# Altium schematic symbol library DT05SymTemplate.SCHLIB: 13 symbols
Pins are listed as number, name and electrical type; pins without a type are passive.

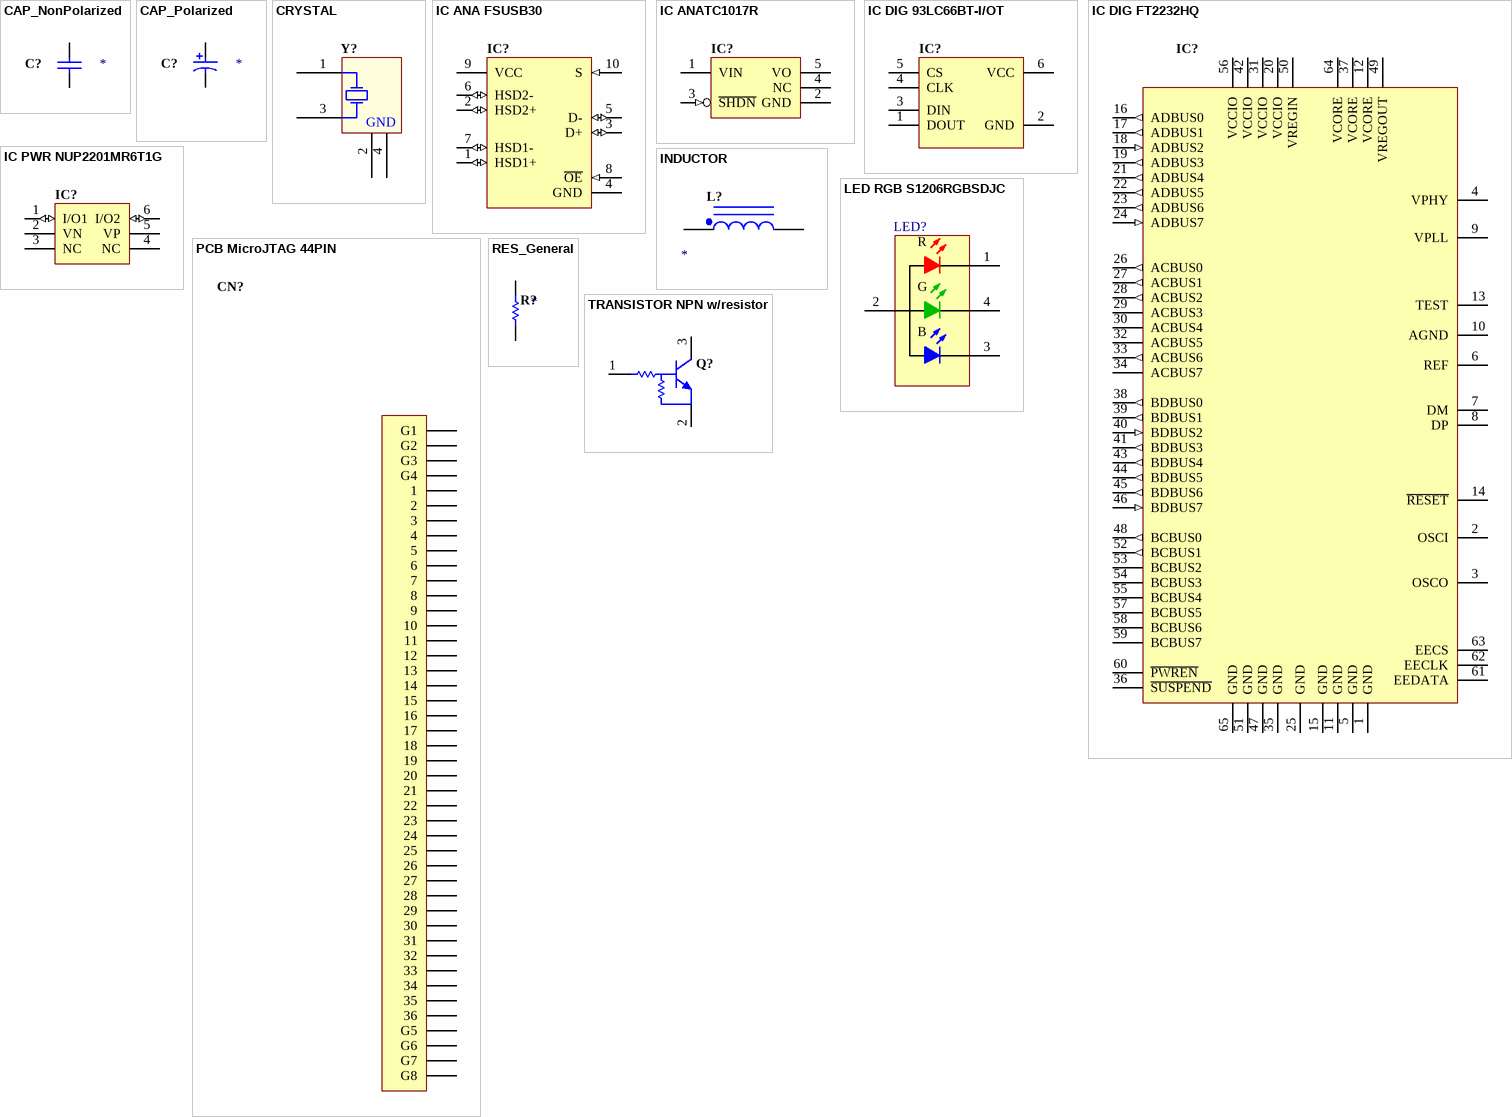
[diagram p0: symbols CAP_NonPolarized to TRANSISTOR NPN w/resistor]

## CAP_NonPolarized
designator C?  (value not drawn)
pins: 1, 2

## CAP_Polarized
designator C?  (value not drawn)
pins: 1, 2

## CRYSTAL
designator Y?  (value not drawn)
pins: 1 X1, 2 GND, 3 X2, 4 GND

## IC ANA FSUSB30
designator IC?  (value not drawn)
IC,Analog,FSUB30,Low-Power, Two-Port, High-Speed USB2.0 Switch
pins: 1 HSD1+ (io) "Data Inport", 2 HSD2+ (io) "Data Inport", 3 D+ (io) "Data Inport", 4 GND (power) "Ground", 5 D- (io) "Data Inport", 6 HSD2- (io) "Data Inport", 7 HSD1- (io) "Data Inport", 8 ~{OE} (in) "Bus Switch Enable", 9 VCC (power) "Supply", 10 S (in) "Select Input"

## IC ANATC1017R
designator IC?, comment IC ANA TC1017R  (value not drawn)
IC,Analog,XC6220B331MR-G,High Current High Speed LDO Regulator
pins: 1 VIN (power), 2 GND (power), 3 ~{SHDN} (in), 4 NC, 5 VO (power)

## IC DIG 93LC66BT-I/OT
designator IC?  (value not drawn)
IC,Digital,93LC66BT-I/OT,4K Microwire Compatible Serial EEPROM
pins: 1 DOUT, 2 GND (power), 3 DIN, 4 CLK, 5 CS (power), 6 VCC

## IC DIG FT2232HQ
designator IC?  (value not drawn)
IC,Digital,FT2232H,DUAL HIGH SPEED USB TO MULTIPURPOSE UART/FIFO IC
pins: 1 GND, 2 OSCI, 3 OSCO, 4 VPHY, 5 GND, 6 REF, 7 DM, 8 DP, 9 VPLL, 10 AGND, 11 GND, 12 VCORE, 13 TEST, 14 ~{RESET}, 15 GND, 16 ADBUS0 (out), 17 ADBUS1 (out), 18 ADBUS2 (in), 19 ADBUS3 (out), 20 VCCIO, 21 ADBUS4 (out), 22 ADBUS5 (out), 23 ADBUS6 (out), 24 ADBUS7 (in), 25 GND, 26 ACBUS0 (out), 27 ACBUS1 (out), 28 ACBUS2 (out), 29 ACBUS3, 30 ACBUS4, 31 VCCIO, 32 ACBUS5, 33 ACBUS6 (out), 34 ACBUS7, 35 GND, 36 ~{SUSPEND}, 37 VCORE, 38 BDBUS0 (out), 39 BDBUS1 (out), 40 BDBUS2 (in), 41 BDBUS3 (out), 42 VCCIO, 43 BDBUS4 (out), 44 BDBUS5 (out), 45 BDBUS6 (out), 46 BDBUS7 (in), 47 GND, 48 BCBUS0 (out), 49 VREGOUT, 50 VREGIN, 51 GND, 52 BCBUS1 (out), 53 BCBUS2, 54 BCBUS3, 55 BCBUS4, 56 VCCIO, 57 BCBUS5, 58 BCBUS6, 59 BCBUS7, 60 ~{PWREN}, 61 EEDATA, 62 EECLK, 63 EECS, 64 VCORE, 65 GND
2 alternate drawings of the same symbol

## IC PWR NUP2201MR6T1G
designator IC?  (value not drawn)
IC,Power,NUP2201MR6T1G,ESD Protection Diodes with Low Clamping Voltage,TSOP-6
pins: 1 I/O1 (io) "Input/Output 1", 2 VN (power), 3 NC, 4 NC, 5 VP (power), 6 I/O2 (io)

## INDUCTOR
designator L?  (value not drawn)
pins: 1, 2

## LED RGB S1206RGBSDJC
designator LED?  (value not drawn)
LED,S1206RGBSDJC,Sansen LED RGB,SMD
pins: 1 R, 2 A2, 3 B, 4 G

## PCB MicroJTAG 44PIN
designator CN?  (value not drawn)
PCB,DT05,MircoJTAG,Altium,44Pin,TH
pins: 1, 2, 3, 4, 5, 6, 7, 8, 9, 10, 11, 12, 13, 14, 15, 16, 17, 18, 19, 20, 21, 22, 23, 24, 25, 26, 27, 28, 29, 30, 31, 32, 33, 34, 35, 36, G1, G2, G3, G4, G5, G6, G7, G8

## RES_General
designator R?  (value not drawn)
pins: 1, 2

## TRANSISTOR NPN w/resistor
designator Q?  (value not drawn)
Transitor,NPN,PDTC143ZE,With Build-in RES,SOT416
pins: 1 B, 2 E, 3 C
